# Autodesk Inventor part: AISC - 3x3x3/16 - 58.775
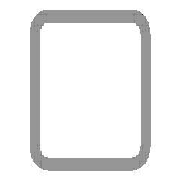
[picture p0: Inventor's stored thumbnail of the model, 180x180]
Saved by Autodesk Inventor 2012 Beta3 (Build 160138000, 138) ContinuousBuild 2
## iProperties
_CCFamilyMember: 9
_CCFamilyDisplayName: ANSI AISC (Square) - Tube
_FrameMemberDoc: Frame Member File
_Version: 15.0.0
_GetPNFromCC: 1
Created: 2011-01
Part Number: AISC - 3x3x3/16 - 58.775
Material: Steel, Mild
Description: Tube
Document SubType Name: Modeling
Standard: ANSI
Designer: Beta-8540w
Standards Organization: ANSI
Language: en-US
Size Designation: 3x3x3/16
Categories: <MemberInstance><Categories><Category DisplayName="Structural Shapes" InternalName="089c4875-fa83-4c05-b084-43b9cc11f5ed" Mnemonic="GRDR"><CategoryParameter Dis
Stock Number: 3x3x3/16
Density: 7.86 g/cm^3
IsCustomPart: 1
G_L: 58.775 in
G_W: 3.000 in
G_H: 3.000 in
+1EAFC555-4950-48CB-9237-33026613FA03+CUTDETAIL1: Cut
Author: Beta-8540w
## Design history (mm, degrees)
node "Start plane"
node "End plane"
sketch "Sketch"
  geometry: L1 (-38.1, -28.575)-(-38.1, 28.575); L2 (-28.575, 38.1)-(28.575, 38.1); L3 (38.1, 28.575)-(38.1, -28.575); L4 (28.575, -38.1)-(-28.575, -38.1); L5 (-28.575, 33.337)-(28.575, 33.338); L6 (33.338, 28.575)-(33.338, -28.575); L7 (28.575, -33.337)-(-28.575, -33.338); L8 (-33.338, -28.575)-(-33.338, 28.575); L9 (0, 56.102)-(0, -56.102) reference; L10 (-56.102, 0)-(56.102, 0) reference; A1 r 9.525 centre (-28.575, -28.575) between (-38.1, -28.575) and (-28.575, -38.1); A2 r 9.525 centre (-28.575, 28.575) between (-28.575, 38.1) and (-38.1, 28.575); A3 r 9.525 centre (28.575, 28.575) between (38.1, 28.575) and (28.575, 38.1); A4 r 9.525 centre (28.575, -28.575) between (28.575, -38.1) and (38.1, -28.575); A5 r 4.763 centre (-28.575, 28.575) between (-28.575, 33.337) and (-33.338, 28.575); A6 r 4.763 centre (28.575, 28.575) between (33.338, 28.575) and (28.575, 33.338); A7 r 4.763 centre (28.575, -28.575) between (28.575, -33.337) and (33.338, -28.575); A8 r 4.763 centre (-28.575, -28.575) between (-33.338, -28.575) and (-28.575, -33.338)
  constraints: 16 end point, 16 point on circle, 8 centre point, 8 tangent, 4 parallel, 3 equal radius, 2 perpendicular, 7 other
  dimensions: "d10" = 76.2 distance between parallel lines of L2 L4 (= G_H); "d11" = 76.2 distance between parallel lines of L1 L3 (= G_W); "d12" = 4.7625 distance between parallel lines of L3 L6 (= G_T); "d15" = 38.1 distance between parallel lines of L2 L10 (= 0.5 x d10); "d16" = 38.1 distance between parallel lines of L9 L3 (= 0.5 x d11); "d17" = 9.525 radius of A1 (= G_IR)
extrude "Body" new body sketch "Sketch" stored distance "d3" = 1492.89148 (= G_L); taper "d4" = 0 deg
node "Driven Length"
  sketch "Sketch3"
    geometry: L1 (0, 0)-(10, 0) reference
    constraints: 2 end point, 1 horizontal
  workplane "Work Plane3"
  sketch "Sketch4"
    geometry: L1 (-2, 31.109)-(12, 31.109) reference; L2 (-2, 1524)-(12, 1524) reference
    dimensions: "d19" = 1492.89148 distance between parallel lines of L1 L2 (derived)
workplane "Work Plane4"
split "Split1"
body "Solid1"
other parameters: "G_W" = 76.2 [user parameter; used in 1 equation term], "G_H" = 76.2 [user parameter; used in 1 equation term], "G_T" = 4.7625 [user parameter; used in 1 equation term], "G_IR" = 9.525 [user parameter; used in 1 equation term], "G_L" = 1492.89148 (= d19) [user parameter; used in 1 equation term], "G_OFFSET_START" = -31.10852 [user parameter; used in 1 equation term], "G_OFFSET_END" = 0 [user parameter; used in 1 equation term], "d13" = 31.10852 (= -G_OFFSET_START), "d14" = 1524 (= G_OFFSET_END + B_L), "B_L" = 1524 [user parameter; used in 1 equation term], "d18" = 90 deg
